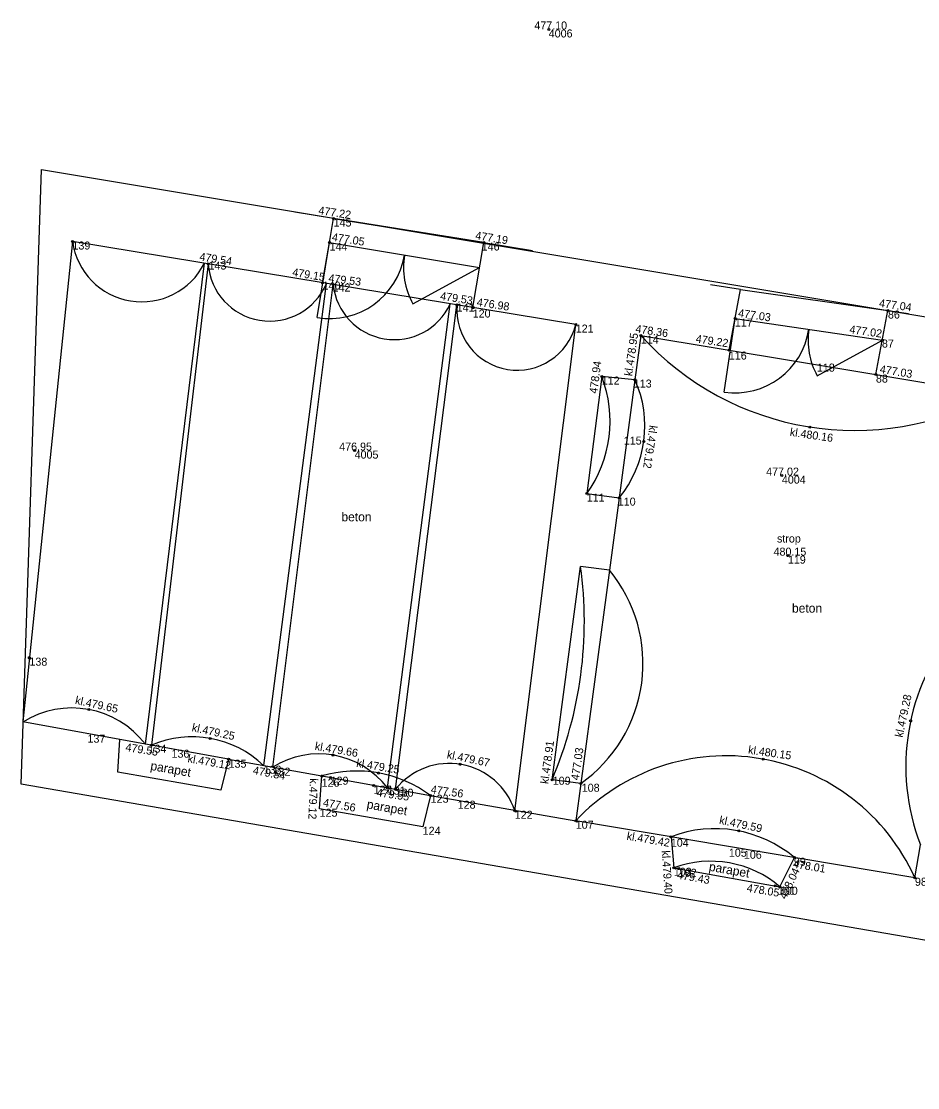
# Model space of a CAD drawing. Extents: x -874376.5 to -874348.6, y -1056301.7 to -1056225.7.
# Drawn here: x -874376.45 to -874367.49, y -1056275.91 to -1056265.25 of the extents above; entities that cross this region are included whole.
import ezdxf

# ---------------------------------------------------------------- set-up
doc = ezdxf.new("R2010")
doc.units = 0
for name, color, linetype in [('Vrstva 1', 7, 'Continuous'), ('Vrstva 2', 7, 'Continuous'), ('Vrstva 3', 7, 'Continuous'), ('Vrstva 57', 7, 'Continuous'), ('Vrstva 6', 7, 'Continuous'), ('Vrstva 60', 7, 'Continuous'), ('Vrstva 61', 7, 'Continuous'), ('Vrstva 62', 7, 'Continuous')]:
    doc.layers.add(name, color=color, linetype=linetype)

msp = doc.modelspace()

# ---------------------------------------------------------------- linework, layer by layer
at = {"layer": 'Vrstva 1'}
for p, q in [((-874373.495, -1056268.21), (-874373.37, -1056267.46)), ((-874373.37, -1056267.46), (-874371.871, -1056267.71)), ((-874375.21, -1056272.475), (-874374.622, -1056267.667)), ((-874374.584, -1056267.674), (-874375.15, -1056272.484)), ((-874372.538, -1056268.074), (-874371.871, -1056267.71)), ((-874374.029, -1056272.687), (-874373.401, -1056267.869)), ((-874373.939, -1056272.704), (-874373.335, -1056267.88)), ((-874372.793, -1056272.911), (-874372.164, -1056268.073)), ((-874372.711, -1056272.926), (-874372.097, -1056268.084)), ((-874369.426, -1056268.955), (-874369.318, -1056268.219)), ((-874369.318, -1056268.219), (-874367.845, -1056268.435)), ((-874368.499, -1056268.791), (-874367.845, -1056268.435)), ((-874370.319, -1056268.831), (-874370.477, -1056270.012)), ((-874370.574, -1056270.735), (-874370.86, -1056272.868)), ((-874374.379, -1056272.625), (-874375.466, -1056272.428)), ((-874373.448, -1056272.792), (-874372.361, -1056272.988))]:
    msp.add_line(p, q, dxfattribs=at)
for centre, radius, start, end in [((-874373.37, -1056267.46), 0.76, 260.5377, 350.5377), ((-874371.871, -1056267.71), 0.76, 170.5377, 208.601), ((-874369.318, -1056268.219), 0.744, 261.6509, 351.6509), ((-874367.845, -1056268.435), 0.744, 171.6509, 208.5893)]:
    msp.add_arc(centre, radius, start, end, dxfattribs=at)
at = {"layer": 'Vrstva 2'}
for p, q in [((-874376.451, -1056272.876), (-874376.25, -1056266.73)), ((-874376.25, -1056266.73), (-874360.04, -1056269.43)), ((-874373.33, -1056267.22), (-874373.716, -1056267.158)), ((-874373.37, -1056267.46), (-874373.33, -1056267.22)), ((-874371.829, -1056267.461), (-874373.33, -1056267.22)), ((-874373.33, -1056267.22), (-874371.829, -1056267.461)), ((-874375.94, -1056267.45), (-874376.437, -1056272.253)), ((-874370.91, -1056268.28), (-874375.94, -1056267.45)), ((-874373.442, -1056267.862), (-874373.37, -1056267.46)), ((-874371.937, -1056268.111), (-874371.829, -1056267.461)), ((-874371.829, -1056267.461), (-874371.342, -1056267.539)), ((-874369.264, -1056267.928), (-874369.565, -1056267.884)), ((-874369.378, -1056268.536), (-874369.264, -1056267.928)), ((-874369.264, -1056267.928), (-874367.79, -1056268.14)), ((-874367.91, -1056268.78), (-874367.79, -1056268.14)), ((-874367.79, -1056268.14), (-874367.583, -1056268.17)), ((-874371.52, -1056273.14), (-874370.91, -1056268.28)), ((-874370.26, -1056268.39), (-874370.319, -1056268.831)), ((-874370.26, -1056268.39), (-874367.91, -1056268.78)), ((-874367.91, -1056268.78), (-874366.725, -1056268.977)), ((-874370.65, -1056268.8), (-874370.8, -1056269.97)), ((-874370.319, -1056268.831), (-874370.65, -1056268.8)), ((-874370.8, -1056269.97), (-874370.477, -1056270.012)), ((-874370.477, -1056270.012), (-874370.574, -1056270.735)), ((-874371.147, -1056272.83), (-874370.861, -1056270.697)), ((-874370.574, -1056270.735), (-874370.861, -1056270.697)), ((-874375.466, -1056272.428), (-874376.437, -1056272.253)), ((-874375.487, -1056272.756), (-874375.466, -1056272.428)), ((-874374.379, -1056272.625), (-874374.457, -1056272.936)), ((-874374.379, -1056272.625), (-874373.449, -1056272.792)), ((-874374.457, -1056272.936), (-874375.487, -1056272.756)), ((-874373.47, -1056273.12), (-874373.449, -1056272.792)), ((-874370.86, -1056272.868), (-874371.147, -1056272.83)), ((-874358.872, -1056275.909), (-874376.451, -1056272.876)), ((-874370.86, -1056272.868), (-874370.91, -1056273.24)), ((-874372.361, -1056272.988), (-874372.44, -1056273.3)), ((-874372.361, -1056272.988), (-874370.91, -1056273.24)), ((-874372.44, -1056273.3), (-874373.47, -1056273.12)), ((-874367.52, -1056273.81), (-874370.91, -1056273.24)), ((-874369.958, -1056273.4), (-874369.93, -1056273.71)), ((-874367.52, -1056273.81), (-874367.466, -1056273.481)), ((-874368.87, -1056273.9), (-874368.725, -1056273.607)), ((-874369.93, -1056273.71), (-874368.87, -1056273.9))]:
    msp.add_line(p, q, dxfattribs=at)
at = {"layer": 'Vrstva 3'}
for centre, radius, start, end in [((-874375.247, -1056267.353), 0.7, 187.9745, 333.2817), ((-874373.969, -1056267.63), 0.616, 184.0935, 337.1606), ((-874372.723, -1056267.816), 0.615, 185.9699, 335.1938), ((-874371.495, -1056268.133), 0.603, 175.3976, 345.8916), ((-874368.123, -1056266.459), 2.88, 222.1024, 299.052), ((-874371.802, -1056269.247), 1.235, 324.175, 21.2135), ((-874371.347, -1056269.294), 1.128, 320.5037, 24.2389), ((-874374.87, -1056271.246), 4.046, 336.9456, 7.7957), ((-874371.705, -1056271.669), 1.467, 305.1764, 39.5556), ((-874365.423, -1056272.697), 2.188, 140.3291, 200.9849), ((-874375.946, -1056273.04), 0.927, 37.5693, 121.9665), ((-874374.745, -1056273.441), 1.039, 46.4797, 113.003), ((-874373.479, -1056273.437), 0.865, 37.4624, 122.0753), ((-874369.406, -1056274.659), 2.068, 24.2338, 136.6771), ((-874372.173, -1056273.355), 0.688, 18.233, 141.3131), ((-874373.102, -1056273.982), 1.239, 53.304, 106.2511), ((-874369.518, -1056274.553), 1.234, 50.03, 110.8839), ((-874369.562, -1056274.711), 1.066, 49.5016, 110.1742)]:
    msp.add_arc(centre, radius, start, end, dxfattribs=at)
at = {"layer": 'Vrstva 57'}
for centre in [(-874371.18, -1056265.33), (-874373.33, -1056267.22), (-874375.94, -1056267.45), (-874373.37, -1056267.46), (-874371.829, -1056267.461), (-874374.584, -1056267.674), (-874373.442, -1056267.862), (-874373.335, -1056267.88), (-874372.097, -1056268.084), (-874371.937, -1056268.111), (-874367.79, -1056268.14), (-874369.318, -1056268.219), (-874370.91, -1056268.28), (-874370.26, -1056268.39), (-874367.845, -1056268.435), (-874369.378, -1056268.536), (-874367.91, -1056268.78), (-874370.65, -1056268.8), (-874370.319, -1056268.831), (-874368.571, -1056269.305), (-874370.23, -1056269.448), (-874373.12, -1056269.54), (-874368.85, -1056269.79), (-874370.8, -1056269.97), (-874370.477, -1056270.012), (-874368.79, -1056270.59), (-874376.371, -1056271.61), (-874375.777, -1056272.129), (-874367.563, -1056272.241), (-874375.15, -1056272.485), (-874374.564, -1056272.417), (-874374.379, -1056272.625), (-874373.336, -1056272.583), (-874369.038, -1056272.624), (-874372.064, -1056272.676), (-874373.449, -1056272.793), (-874373.361, -1056272.808), (-874372.881, -1056272.763), (-874371.147, -1056272.83), (-874372.93, -1056272.887), (-874372.793, -1056272.911), (-874372.711, -1056272.926), (-874370.86, -1056272.868), (-874372.361, -1056272.988), (-874371.52, -1056273.14), (-874370.91, -1056273.24), (-874369.28, -1056273.342), (-874369.958, -1056273.4), (-874368.725, -1056273.607), (-874369.93, -1056273.71), (-874369.88, -1056273.719), (-874368.918, -1056273.891), (-874368.87, -1056273.9), (-874367.52, -1056273.81)]:
    msp.add_circle(centre, 0.01, dxfattribs=at)
at = {"layer": 'Vrstva 60'}
for p, q in [((-874371.18, -1056265.33), (-874371.18, -1056265.33)), ((-874373.33, -1056267.22), (-874373.33, -1056267.22)), ((-874375.94, -1056267.45), (-874375.94, -1056267.45)), ((-874373.37, -1056267.46), (-874373.37, -1056267.46)), ((-874371.85, -1056267.46), (-874371.85, -1056267.46)), ((-874374.58, -1056267.65), (-874374.58, -1056267.65)), ((-874373.44, -1056267.85), (-874373.44, -1056267.85)), ((-874373.34, -1056267.87), (-874373.34, -1056267.87)), ((-874372.1, -1056268.07), (-874372.1, -1056268.07)), ((-874371.94, -1056268.13), (-874371.94, -1056268.13)), ((-874367.79, -1056268.14), (-874367.79, -1056268.14)), ((-874369.32, -1056268.22), (-874369.32, -1056268.22)), ((-874370.91, -1056268.28), (-874370.91, -1056268.28)), ((-874370.26, -1056268.39), (-874370.26, -1056268.39)), ((-874367.85, -1056268.43), (-874367.85, -1056268.43)), ((-874369.38, -1056268.55), (-874369.38, -1056268.55)), ((-874368.5, -1056268.67), (-874368.5, -1056268.67)), ((-874367.91, -1056268.78), (-874367.91, -1056268.78)), ((-874370.65, -1056268.8), (-874370.65, -1056268.8)), ((-874370.33, -1056268.83), (-874370.33, -1056268.83)), ((-874370.43, -1056269.4), (-874370.43, -1056269.4)), ((-874373.12, -1056269.54), (-874373.12, -1056269.54)), ((-874368.85, -1056269.79), (-874368.85, -1056269.79)), ((-874370.8, -1056269.97), (-874370.8, -1056269.97)), ((-874370.49, -1056270.01), (-874370.49, -1056270.01)), ((-874368.79, -1056270.59), (-874368.79, -1056270.59)), ((-874376.37, -1056271.61), (-874376.37, -1056271.61)), ((-874375.79, -1056272.38), (-874375.79, -1056272.38)), ((-874375.18, -1056272.48), (-874375.18, -1056272.48)), ((-874374.95, -1056272.53), (-874374.95, -1056272.53)), ((-874374.38, -1056272.63), (-874374.38, -1056272.63)), ((-874374.03, -1056272.69), (-874374.03, -1056272.69)), ((-874373.94, -1056272.71), (-874373.94, -1056272.71)), ((-874373.45, -1056272.82), (-874373.45, -1056272.82)), ((-874373.36, -1056272.8), (-874373.36, -1056272.8)), ((-874371.14, -1056272.8), (-874371.14, -1056272.8)), ((-874372.93, -1056272.89), (-874372.93, -1056272.89)), ((-874372.79, -1056272.9), (-874372.79, -1056272.9)), ((-874372.71, -1056272.92), (-874372.71, -1056272.92)), ((-874370.85, -1056272.87), (-874370.85, -1056272.87)), ((-874372.36, -1056272.98), (-874372.36, -1056272.98)), ((-874372.09, -1056273.04), (-874372.09, -1056273.04)), ((-874373.47, -1056273.12), (-874373.47, -1056273.12)), ((-874371.52, -1056273.14), (-874371.52, -1056273.14)), ((-874370.91, -1056273.24), (-874370.91, -1056273.24)), ((-874372.44, -1056273.3), (-874372.44, -1056273.3)), ((-874369.96, -1056273.42), (-874369.96, -1056273.42)), ((-874369.38, -1056273.52), (-874369.38, -1056273.52)), ((-874369.23, -1056273.54), (-874369.23, -1056273.54)), ((-874368.73, -1056273.61), (-874368.73, -1056273.61)), ((-874369.93, -1056273.71), (-874369.93, -1056273.71)), ((-874369.88, -1056273.72), (-874369.88, -1056273.72)), ((-874367.52, -1056273.81), (-874367.52, -1056273.81)), ((-874368.89, -1056273.9), (-874368.89, -1056273.9)), ((-874368.87, -1056273.9), (-874368.87, -1056273.9))]:
    msp.add_line(p, q, dxfattribs=at)

# ---------------------------------------------------------------- texts
at = {"layer": 'Vrstva 6'}
for p in [(-874373.252, -1056270.247), (-874368.749, -1056271.16)]:
    msp.add_text('beton', height=0.09, dxfattribs=at).set_placement(p)
for p in [(-874375.166, -1056272.731), (-874373.004, -1056273.116), (-874369.584, -1056273.739)]:
    msp.add_text('parapet', height=0.09, rotation=350.0123, dxfattribs=at).set_placement(p)
at = {"layer": 'Vrstva 61'}
for s, p in [('4006', (-874371.18, -1056265.41)), ('145', (-874373.33, -1056267.3)), ('139', (-874375.94, -1056267.53)), ('144', (-874373.37, -1056267.54)), ('146', (-874371.85, -1056267.54)), ('143', (-874374.58, -1056267.73)), ('140', (-874373.44, -1056267.93)), ('142', (-874373.34, -1056267.95)), ('141', (-874372.1, -1056268.15)), ('120', (-874371.94, -1056268.21)), ('86', (-874367.79, -1056268.22)), ('117', (-874369.32, -1056268.3)), ('121', (-874370.91, -1056268.36)), ('114', (-874370.26, -1056268.47)), ('87', (-874367.85, -1056268.51)), ('116', (-874369.38, -1056268.63)), ('118', (-874368.5, -1056268.75)), ('88', (-874367.91, -1056268.86)), ('112', (-874370.65, -1056268.88)), ('113', (-874370.33, -1056268.91)), ('115', (-874370.43, -1056269.48)), ('4005', (-874373.12, -1056269.62)), ('4004', (-874368.85, -1056269.87)), ('111', (-874370.8, -1056270.05)), ('110', (-874370.49, -1056270.09)), ('119', (-874368.79, -1056270.67)), ('138', (-874376.37, -1056271.69)), ('137', (-874375.79, -1056272.46)), ('134', (-874375.18, -1056272.56)), ('136', (-874374.95, -1056272.61)), ('135', (-874374.38, -1056272.71)), ('133', (-874374.03, -1056272.77)), ('132', (-874373.94, -1056272.79)), ('126', (-874373.45, -1056272.9)), ('129', (-874373.36, -1056272.88)), ('109', (-874371.14, -1056272.88)), ('127', (-874372.93, -1056272.97)), ('131', (-874372.79, -1056272.98)), ('130', (-874372.71, -1056273)), ('108', (-874370.85, -1056272.95)), ('123', (-874372.36, -1056273.06)), ('128', (-874372.09, -1056273.12)), ('125', (-874373.47, -1056273.2)), ('122', (-874371.52, -1056273.22)), ('107', (-874370.91, -1056273.32)), ('124', (-874372.44, -1056273.38)), ('104', (-874369.96, -1056273.5)), ('105', (-874369.38, -1056273.6)), ('106', (-874369.23, -1056273.62)), ('99', (-874368.73, -1056273.69)), ('103', (-874369.93, -1056273.79)), ('102', (-874369.88, -1056273.8)), ('98', (-874367.52, -1056273.89)), ('101', (-874368.89, -1056273.98)), ('100', (-874368.87, -1056273.98))]:
    msp.add_text(s, height=0.08, dxfattribs=at).set_placement(p)
at = {"layer": 'Vrstva 62'}
for s, p in [('477.10', (-874371.324, -1056265.33)), ('476.95', (-874373.274, -1056269.54)), ('477.02', (-874369.007, -1056269.79)), ('strop', (-874368.899, -1056270.459)), ('480.15', (-874368.933, -1056270.59))]:
    msp.add_text(s, height=0.08, dxfattribs=at).set_placement(p)
for s, rotation, p in [('477.22', 351.4747, (-874373.486, -1056267.176)), ('477.05', 351.0221, (-874373.351, -1056267.442)), ('477.19', 350.737, (-874371.918, -1056267.426)), ('479.54', 351.1582, (-874374.675, -1056267.638)), ('479.15', 350.6224, (-874373.747, -1056267.793)), ('479.53', 352.8185, (-874373.385, -1056267.853)), ('479.53', 351.1684, (-874372.269, -1056268.031)), ('476.98', 351.4172, (-874371.903, -1056268.093)), ('477.04', 351.9905, (-874367.883, -1056268.103)), ('477.03', 351.663, (-874369.291, -1056268.202)), ('478.36', 351.5134, (-874370.317, -1056268.359)), ('477.02', 351.8652, (-874368.179, -1056268.365)), ('kl.478.95', 82.0154, (-874370.346, -1056268.799)), ('479.22', 351.5546, (-874369.715, -1056268.459)), ('478.94', 82.5897, (-874370.696, -1056268.974)), ('477.03', 350.6797, (-874367.876, -1056268.762)), ('kl.479.12', 261.5088, (-874370.173, -1056269.283)), ('kl.480.16', 351.7595, (-874368.774, -1056269.392)), ('kl.479.28', 78.0002, (-874367.643, -1056272.412)), ('kl.479.65', 347.81, (-874375.918, -1056272.071)), ('kl.479.25', 347.9394, (-874374.752, -1056272.344)), ('479.55', 351.0749, (-874375.414, -1056272.542)), ('kl.479.66', 350.2978, (-874373.522, -1056272.531)), ('kl.478.91', 82.2434, (-874371.185, -1056272.876)), ('477.03', 81.8832, (-874370.879, -1056272.839)), ('kl.480.15', 352.0469, (-874369.191, -1056272.569)), ('kl.479.12', 350.3527, (-874374.793, -1056272.655)), ('kl.479.25', 350.6478, (-874373.107, -1056272.7)), ('kl.479.67', 348.4611, (-874372.203, -1056272.615)), ('479.54', 349.2869, (-874374.141, -1056272.772)), ('k.479.12', 267.8318, (-874373.567, -1056272.815)), ('479.55', 351.9266, (-874372.904, -1056272.995)), ('477.56', 351.816, (-874372.363, -1056272.964)), ('477.56', 350.1711, (-874373.44, -1056273.095)), ('kl.479.59', 348.2162, (-874369.481, -1056273.269)), ('kl.479.42', 350.3857, (-874370.405, -1056273.429)), ('kl.479.40', 273.8459, (-874370.051, -1056273.54)), ('478.01', 350.7425, (-874368.743, -1056273.708)), ('479.43', 350.2716, (-874369.901, -1056273.818)), ('478.04', 64.3311, (-874368.81, -1056274.032)), ('478.05', 350.656, (-874369.205, -1056273.948))]:
    msp.add_text(s, height=0.08, rotation=rotation, dxfattribs=at).set_placement(p)

doc.saveas('drawing.dxf')
